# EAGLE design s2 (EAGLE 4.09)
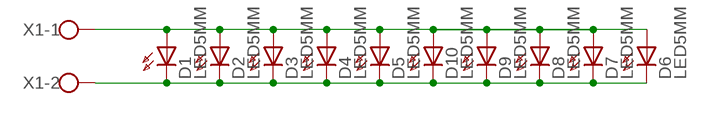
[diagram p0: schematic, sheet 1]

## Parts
D1  LED5MM  [LED5MM]
D2  LED5MM  [LED5MM]
D3  LED5MM  [LED5MM]
D4  LED5MM  [LED5MM]
D5  LED5MM  [LED5MM]
D6  LED5MM  [LED5MM]
D7  LED5MM  [LED5MM]
D8  LED5MM  [LED5MM]
D9  LED5MM  [LED5MM]
D10  LED5MM  [LED5MM]
X1  W237-102  [W237-102]

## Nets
N$1: D1.K(C) D2.K(C) D3.K(C) D4.K(C) D5.K(C) D6.K(C) D7.K(C) D8.K(C) D9.K(C) D10.K(C) X1.2
N$2: D1.A D2.A D3.A D4.A D5.A D6.A D7.A D8.A D9.A D10.A X1.1

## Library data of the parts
D1-D10 = Diody - LED:LED5MM: LED
X1 = Konektory - Wago 2:W237-102: WAGO SCREW CLAMP

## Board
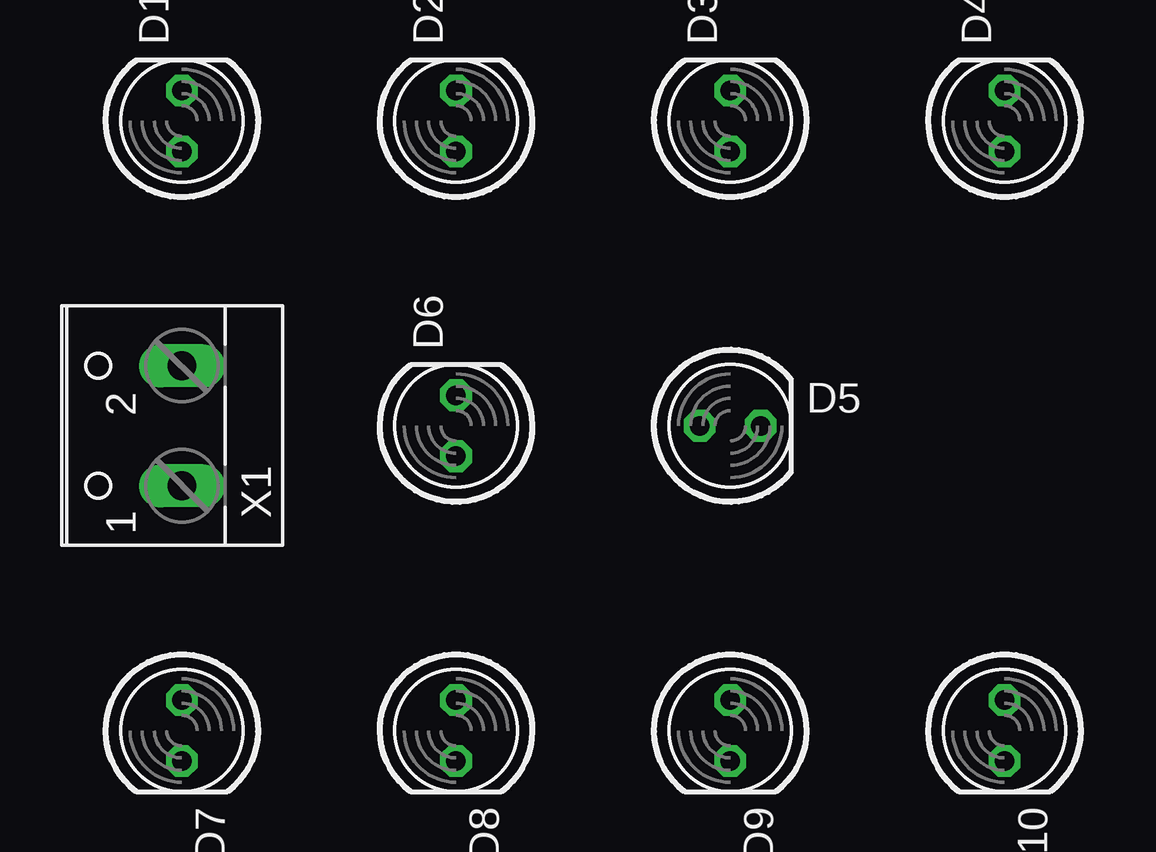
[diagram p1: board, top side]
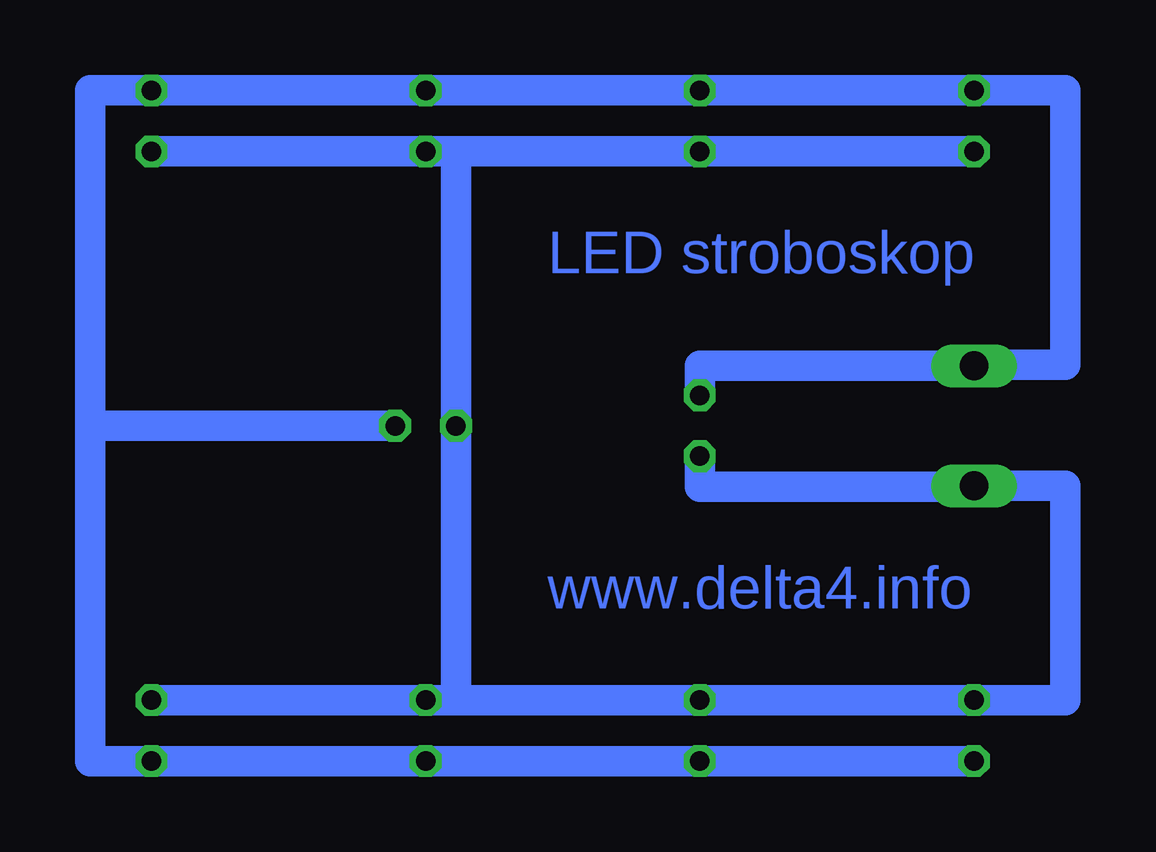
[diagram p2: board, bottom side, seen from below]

No outline drawn. Coordinates in mm, seen from the top.
Copper layers 16: Bottom 0.035mm
Design rules "default": minimum track width 10mil, minimum drill 24mil, track to track 8mil, track to pad 8mil, pad to pad 8mil, via to via 8mil, smd to smd 8mil, copper to edge 40mil, drill to drill 8mil, minimum pad ring 10mil, minimum via ring 8mil, stop-mask expansion 4mil, vias tented up to drill 0mil, thermal gap 10mil

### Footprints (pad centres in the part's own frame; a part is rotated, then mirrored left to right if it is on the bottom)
LED5MM = drill 0.813 octagon: A -1.27,0; K 1.27,0
W237-102 = drill 1.194 long: 1 -2.5,-1.27; 2 2.5,-1.27

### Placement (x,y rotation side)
D1  7.62,52.07 90 top
D2  19.05,52.07 90 top
D3  30.48,52.07 90 top
D4  41.91,52.07 90 top
D5  30.48,39.37 0 top
D6  19.05,39.37 90 top
D7  7.62,26.67 270 top
D8  19.05,26.67 270 top
D9  30.48,26.67 270 top
D10  41.91,26.67 270 top
X1  6.35,39.37 90 top

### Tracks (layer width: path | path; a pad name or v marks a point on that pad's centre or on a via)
N$1
  Bottom 1.27: D6.K 19.05,41.87 X1.2 7.62,41.91 3.81,41.91 3.81,53.34 D1.K D2.K D3.K D4.K 44.45,53.34 44.45,39.37 | 44.45,39.37 44.45,25.4 D10.K D9.K D8.K D7.K | 44.45,39.37 D5.K
N$2
  Bottom 1.27: D1.A D2.A D3.A D4.A 29.21,50.8 D5.A 29.21,27.94 D10.A D9.A D8.A D7.A 3.81,27.94 3.81,36.87 X1.1 7.62,36.83 19.05,36.83 D6.A

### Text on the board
Bottom: LED stroboskop | www.delta4.info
